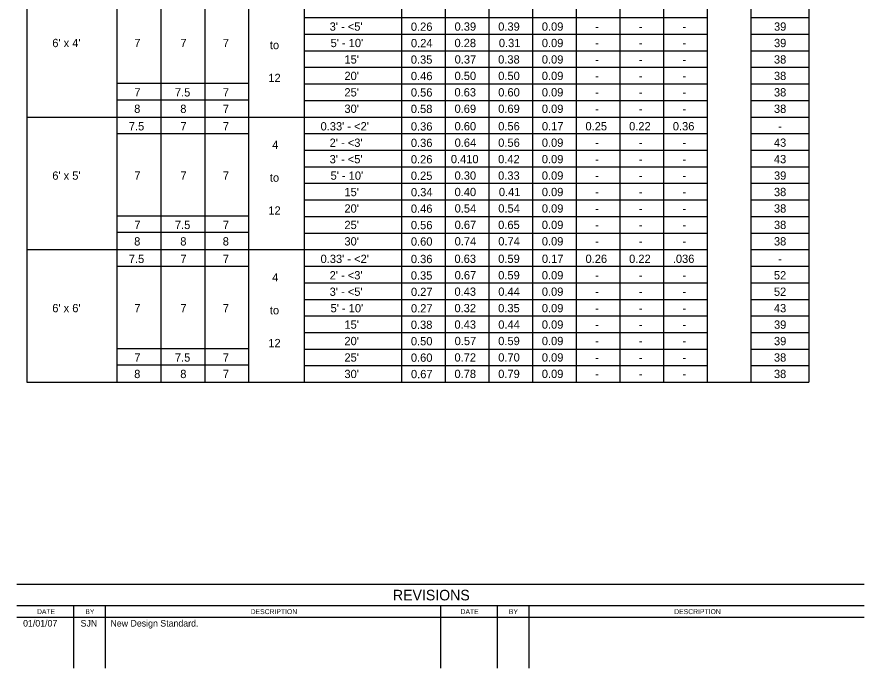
# Model space of a CAD drawing. Extents: x 10340.93 to 10343.14, y 76399.51 to 76400.59.
# Drawn here: x 10340.931 to 10341.575, y 76399.507 to 76400.002 of the extents above; entities that cross this region are included whole.
import ezdxf

# ---------------------------------------------------------------- set-up
doc = ezdxf.new("R2010")
doc.units = 0
for name, color, linetype in [('AdhocPoint_dp', 7, 'Continuous'), ('Border', 7, 'Continuous'), ('PlotBorder_dp', 7, 'Continuous')]:
    doc.layers.add(name, color=color, linetype=linetype)

msp = doc.modelspace()

# ---------------------------------------------------------------- linework, layer by layer
at = {"layer": 'Border'}
for p, q in [((10341.57483, 76399.57), (10340.93072, 76399.57)), ((10341.57483, 76399.5539), (10340.93072, 76399.5539)), ((10340.97374, 76399.5539), (10340.97374, 76399.50656)), ((10340.99791, 76399.5539), (10340.99791, 76399.50656)), ((10341.25278, 76399.5539), (10341.25278, 76399.50656)), ((10341.2958, 76399.5539), (10341.2958, 76399.50656)), ((10341.31997, 76399.5539), (10341.31997, 76399.50656)), ((10340.93072, 76399.54537), (10341.57483, 76399.54537))]:
    msp.add_line(p, q, dxfattribs=at)
at = {"layer": 'PlotBorder_dp'}
for p, q in [((10340.93815, 76400.49971), (10340.93815, 76399.72389)), ((10341.53289, 76400.49971), (10341.53289, 76399.72389)), ((10341.00679, 76400.47984), (10341.00679, 76399.72389)), ((10341.14923, 76400.47984), (10341.14923, 76399.72389)), ((10341.22311, 76400.47984), (10341.22311, 76399.72389)), ((10341.4887, 76400.47984), (10341.4887, 76399.72389)), ((10341.04015, 76400.46724), (10341.04015, 76399.72389)), ((10341.07351, 76400.46724), (10341.07351, 76399.72389)), ((10341.10687, 76400.46724), (10341.10687, 76399.72389)), ((10341.25631, 76400.44209), (10341.25631, 76399.72389)), ((10341.28951, 76400.44209), (10341.28951, 76399.72389)), ((10341.32271, 76400.44209), (10341.32271, 76399.72389)), ((10341.35591, 76400.44209), (10341.35591, 76399.72389)), ((10341.3891, 76400.44209), (10341.3891, 76399.72389)), ((10341.3891, 76400.44209), (10341.3891, 76399.72389)), ((10341.4223, 76400.44209), (10341.4223, 76399.72389)), ((10341.4555, 76400.44209), (10341.4555, 76399.72389)), ((10341.14923, 76400.00109), (10341.4555, 76400.00109)), ((10341.4887, 76400.00109), (10341.53289, 76400.00109)), ((10341.14923, 76399.98849), (10341.4555, 76399.98849)), ((10341.4887, 76399.98849), (10341.53289, 76399.98849)), ((10341.14923, 76399.97589), (10341.4555, 76399.97589)), ((10341.4887, 76399.97589), (10341.53289, 76399.97589)), ((10341.14923, 76399.96329), (10341.4555, 76399.96329)), ((10341.4887, 76399.96329), (10341.53289, 76399.96329)), ((10341.00679, 76399.95117), (10341.10687, 76399.95117)), ((10341.14923, 76399.95069), (10341.4555, 76399.95069)), ((10341.4887, 76399.95069), (10341.53289, 76399.95069)), ((10341.00679, 76399.93867), (10341.10687, 76399.93867)), ((10341.14923, 76399.93809), (10341.4555, 76399.93809)), ((10341.4887, 76399.93809), (10341.53289, 76399.93809)), ((10340.93815, 76399.92549), (10341.4555, 76399.92549)), ((10341.14985, 76399.92549), (10341.22203, 76399.92549)), ((10341.14985, 76399.92549), (10341.22203, 76399.92549)), ((10341.4887, 76399.92549), (10341.53289, 76399.92549)), ((10341.00679, 76399.91289), (10341.10687, 76399.91289)), ((10341.14923, 76399.91289), (10341.4555, 76399.91289)), ((10341.4887, 76399.91289), (10341.53289, 76399.91289)), ((10341.14923, 76399.90029), (10341.4555, 76399.90029)), ((10341.4887, 76399.90029), (10341.53289, 76399.90029)), ((10341.14923, 76399.88769), (10341.4555, 76399.88769)), ((10341.4887, 76399.88769), (10341.53289, 76399.88769)), ((10341.14923, 76399.87509), (10341.4555, 76399.87509)), ((10341.4887, 76399.87509), (10341.53289, 76399.87509)), ((10341.14923, 76399.86249), (10341.4555, 76399.86249)), ((10341.4887, 76399.86249), (10341.53289, 76399.86249)), ((10341.00679, 76399.85037), (10341.10687, 76399.85037)), ((10341.14923, 76399.84989), (10341.4555, 76399.84989)), ((10341.4887, 76399.84989), (10341.53289, 76399.84989)), ((10341.00679, 76399.83787), (10341.10687, 76399.83787)), ((10341.14923, 76399.83729), (10341.4555, 76399.83729)), ((10341.4887, 76399.83729), (10341.53289, 76399.83729)), ((10340.93815, 76399.82469), (10341.4555, 76399.82469)), ((10341.14985, 76399.82469), (10341.22203, 76399.82469)), ((10341.14985, 76399.82469), (10341.22203, 76399.82469)), ((10341.14985, 76399.82469), (10341.22203, 76399.82469)), ((10341.4887, 76399.82469), (10341.53289, 76399.82469)), ((10341.00679, 76399.81209), (10341.10687, 76399.81209)), ((10341.14923, 76399.81209), (10341.4555, 76399.81209)), ((10341.4887, 76399.81209), (10341.53289, 76399.81209)), ((10341.14923, 76399.79949), (10341.4555, 76399.79949)), ((10341.4887, 76399.79949), (10341.53289, 76399.79949)), ((10341.14923, 76399.78689), (10341.4555, 76399.78689)), ((10341.4887, 76399.78689), (10341.53289, 76399.78689)), ((10341.14923, 76399.77429), (10341.4555, 76399.77429)), ((10341.4887, 76399.77429), (10341.53289, 76399.77429)), ((10341.14923, 76399.76169), (10341.4555, 76399.76169)), ((10341.4887, 76399.76169), (10341.53289, 76399.76169)), ((10341.00679, 76399.74957), (10341.10687, 76399.74957)), ((10341.14923, 76399.74909), (10341.4555, 76399.74909)), ((10341.4887, 76399.74909), (10341.53289, 76399.74909)), ((10341.00679, 76399.73707), (10341.10687, 76399.73707)), ((10341.14923, 76399.73649), (10341.4555, 76399.73649)), ((10341.4887, 76399.73649), (10341.53289, 76399.73649)), ((10340.93815, 76399.72389), (10341.53289, 76399.72389)), ((10341.14985, 76399.72389), (10341.22203, 76399.72389))]:
    msp.add_line(p, q, dxfattribs=at)

# ---------------------------------------------------------------- texts
at = {"layer": 'AdhocPoint_dp'}
for s, height, p in [('REVISIONS', 0.008022, (10341.21661, 76399.55802)), ('BY', 0.003753, (10340.98272, 76399.54758)), ('BY', 0.003753, (10341.30479, 76399.54758)), ('01/01/07', 0.005, (10340.93539, 76399.53811)), ('SJN', 0.005, (10340.97912, 76399.53811)), ('New Design Standard.', 0.005, (10341.00182, 76399.53811))]:
    msp.add_text(s, height=height, dxfattribs=at).set_placement(p)
for s, height, rotation, p in [('DATE', 0.003737, 359.86925, (10340.94598, 76399.5476)), ('DESCRIPTION', 0.0037522, 0.04975, (10341.10841, 76399.54756)), ('DATE', 0.003737, 359.86925, (10341.26805, 76399.5476)), ('DESCRIPTION', 0.0037522, 0.04975, (10341.43048, 76399.54756))]:
    msp.add_text(s, height=height, rotation=rotation, dxfattribs=at).set_placement(p)
at = {"layer": 'PlotBorder_dp'}
for s, p in [("3' - <5'", (10341.16849, 76399.99114)), ('0.26', (10341.23025, 76399.99104)), ('0.39', (10341.26345, 76399.99114)), ('0.39', (10341.29665, 76399.99114)), ('0.09', (10341.32981, 76399.99114)), ('-', (10341.37038, 76399.99114)), ('-', (10341.40359, 76399.99114)), ('-', (10341.43677, 76399.99114)), ('39', (10341.50636, 76399.99114)), ("6' x 4'", (10340.95759, 76399.97864)), ('7', (10341.01998, 76399.97862)), ('7', (10341.05502, 76399.97862)), ('7', (10341.08731, 76399.97862)), ("5' - 10'", (10341.1692, 76399.97864)), ('0.24', (10341.23031, 76399.97854)), ('0.28', (10341.2634, 76399.97864)), ('0.31', (10341.29715, 76399.97864)), ('0.09', (10341.32981, 76399.97864)), ('39', (10341.50636, 76399.97864)), ('to', (10341.12303, 76399.97709)), ('-', (10341.37038, 76399.97864)), ('-', (10341.40359, 76399.97864)), ('-', (10341.43677, 76399.97864)), ("15'", (10341.17972, 76399.96614)), ('0.35', (10341.23021, 76399.96604)), ('0.37', (10341.26353, 76399.96614)), ('0.38', (10341.2966, 76399.96614)), ('0.09', (10341.32981, 76399.96614)), ('38', (10341.50631, 76399.96614)), ('-', (10341.37038, 76399.96614)), ('-', (10341.40359, 76399.96614)), ('-', (10341.43677, 76399.96614)), ("20'", (10341.17972, 76399.95364)), ('0.46', (10341.23025, 76399.95354)), ('0.50', (10341.26346, 76399.95364)), ('0.50', (10341.29667, 76399.95364)), ('0.09', (10341.32981, 76399.95364)), ('38', (10341.50631, 76399.95364)), ('12', (10341.12186, 76399.95209)), ('-', (10341.37038, 76399.95364)), ('-', (10341.40359, 76399.95364)), ('-', (10341.43677, 76399.95364)), ('7', (10341.01998, 76399.94112)), ('7.5', (10341.05084, 76399.94112)), ('7', (10341.08731, 76399.94112)), ("25'", (10341.17972, 76399.94114)), ('0.56', (10341.23025, 76399.94104)), ('0.63', (10341.26338, 76399.94114)), ('0.60', (10341.29667, 76399.94114)), ('0.09', (10341.32981, 76399.94114)), ('38', (10341.50631, 76399.94114)), ('-', (10341.37038, 76399.94114)), ('-', (10341.40359, 76399.94114)), ('-', (10341.43677, 76399.94114)), ('8', (10341.01986, 76399.92862)), ('8', (10341.0549, 76399.92862)), ('7', (10341.08731, 76399.92862)), ("30'", (10341.17972, 76399.92864)), ('0.58', (10341.23021, 76399.92854)), ('0.69', (10341.26345, 76399.92864)), ('0.69', (10341.29665, 76399.92864)), ('0.09', (10341.32981, 76399.92864)), ('38', (10341.50631, 76399.92864)), ('-', (10341.37038, 76399.92864)), ('-', (10341.40359, 76399.92864)), ('-', (10341.43677, 76399.92864)), ('7.5', (10341.0158, 76399.91532)), ('7', (10341.05502, 76399.91532)), ('7', (10341.08731, 76399.91532)), ("0.33' - <2'", (10341.16159, 76399.91531)), ('0.36', (10341.23025, 76399.91521)), ('0.60', (10341.26346, 76399.91536)), ('0.56', (10341.29665, 76399.91536)), ('0.17', (10341.32989, 76399.91536)), ('0.25', (10341.363, 76399.91536)), ('0.22', (10341.39619, 76399.91536)), ('0.36', (10341.42943, 76399.91536)), ('-', (10341.50962, 76399.91536)), ('4', (10341.12481, 76399.90129)), ("2' - <3'", (10341.16849, 76399.90281)), ('0.36', (10341.23025, 76399.90271)), ('0.64', (10341.26351, 76399.90286)), ('0.56', (10341.29665, 76399.90286)), ('0.09', (10341.32981, 76399.90286)), ('43', (10341.50629, 76399.90286)), ('-', (10341.37038, 76399.90286)), ('-', (10341.40359, 76399.90286)), ('-', (10341.43677, 76399.90286)), ("3' - <5'", (10341.16849, 76399.89031)), ('0.26', (10341.23025, 76399.89021)), ('0.410', (10341.26064, 76399.89036)), ('0.42', (10341.29659, 76399.89036)), ('0.09', (10341.32981, 76399.89036)), ('43', (10341.50629, 76399.89036)), ('-', (10341.37038, 76399.89036)), ('-', (10341.40359, 76399.89036)), ('-', (10341.43677, 76399.89036)), ("6' x 5'", (10340.95759, 76399.87781)), ('7', (10341.01998, 76399.87782)), ('7', (10341.05502, 76399.87782)), ('7', (10341.08731, 76399.87782)), ('to', (10341.12303, 76399.87629)), ("5' - 10'", (10341.1692, 76399.87781)), ('0.25', (10341.23021, 76399.87771)), ('0.30', (10341.26346, 76399.87786)), ('0.33', (10341.29658, 76399.87786)), ('0.09', (10341.32981, 76399.87786)), ('39', (10341.50636, 76399.87786)), ('-', (10341.37038, 76399.87786)), ('-', (10341.40359, 76399.87786)), ('-', (10341.43677, 76399.87786)), ("15'", (10341.17972, 76399.86531)), ('0.34', (10341.23031, 76399.86521)), ('0.40', (10341.26346, 76399.86536)), ('0.41', (10341.29715, 76399.86536)), ('0.09', (10341.32981, 76399.86536)), ('38', (10341.50631, 76399.86536)), ('-', (10341.37038, 76399.86536)), ('-', (10341.40359, 76399.86536)), ('-', (10341.43677, 76399.86536)), ('12', (10341.12186, 76399.85129)), ("20'", (10341.17972, 76399.85281)), ('0.46', (10341.23025, 76399.85271)), ('0.54', (10341.26351, 76399.85286)), ('0.54', (10341.29671, 76399.85286)), ('0.09', (10341.32981, 76399.85286)), ('38', (10341.50631, 76399.85286)), ('-', (10341.37038, 76399.85286)), ('-', (10341.40359, 76399.85286)), ('-', (10341.43677, 76399.85286)), ('7', (10341.01998, 76399.84032)), ('7.5', (10341.05084, 76399.84032)), ('7', (10341.08731, 76399.84032)), ("25'", (10341.17972, 76399.84031)), ('0.56', (10341.23025, 76399.84021)), ('0.67', (10341.26353, 76399.84036)), ('0.65', (10341.29661, 76399.84036)), ('0.09', (10341.32981, 76399.84036)), ('-', (10341.37038, 76399.84036)), ('-', (10341.40359, 76399.84036)), ('-', (10341.43677, 76399.84036)), ('38', (10341.50631, 76399.84036)), ('8', (10341.01986, 76399.82782)), ('8', (10341.0549, 76399.82782)), ('8', (10341.08719, 76399.82782)), ("30'", (10341.17972, 76399.82781)), ('0.60', (10341.23027, 76399.82771)), ('0.74', (10341.26351, 76399.82786)), ('0.74', (10341.29671, 76399.82786)), ('0.09', (10341.32981, 76399.82786)), ('-', (10341.37038, 76399.82786)), ('-', (10341.40359, 76399.82786)), ('-', (10341.43677, 76399.82786)), ('38', (10341.50631, 76399.82786)), ('7.5', (10341.0158, 76399.81452)), ('7', (10341.05502, 76399.81452)), ('7', (10341.08731, 76399.81452)), ("0.33' - <2'", (10341.16159, 76399.81453)), ('0.36', (10341.23025, 76399.81442)), ('0.63', (10341.26338, 76399.81458)), ('0.59', (10341.29665, 76399.81458)), ('0.17', (10341.32989, 76399.81458)), ('0.26', (10341.36304, 76399.81458)), ('0.22', (10341.39619, 76399.81458)), ('.036', (10341.42943, 76399.81458)), ('-', (10341.50962, 76399.81453)), ('4', (10341.12481, 76399.80049)), ("2' - <3'", (10341.16849, 76399.80203)), ('0.35', (10341.23021, 76399.80192)), ('0.67', (10341.26353, 76399.80208)), ('0.59', (10341.29665, 76399.80208)), ('0.09', (10341.32981, 76399.80208)), ('-', (10341.37038, 76399.80208)), ('-', (10341.40359, 76399.80208)), ('-', (10341.43677, 76399.80208)), ('52', (10341.50629, 76399.80203)), ("3' - <5'", (10341.16849, 76399.78953)), ('0.27', (10341.23033, 76399.78942)), ('0.43', (10341.26338, 76399.78958)), ('0.44', (10341.29671, 76399.78958)), ('0.09', (10341.32981, 76399.78958)), ('-', (10341.37038, 76399.78958)), ('-', (10341.40359, 76399.78958)), ('-', (10341.43677, 76399.78958)), ('52', (10341.50629, 76399.78953)), ("6' x 6'", (10340.95759, 76399.77708)), ('7', (10341.01998, 76399.77702)), ('7', (10341.05502, 76399.77702)), ('7', (10341.08731, 76399.77702)), ('to', (10341.12303, 76399.77549)), ("5' - 10'", (10341.1692, 76399.77703)), ('0.27', (10341.23033, 76399.77692)), ('0.32', (10341.26339, 76399.77708)), ('0.35', (10341.29661, 76399.77708)), ('0.09', (10341.32981, 76399.77708)), ('-', (10341.37038, 76399.77708)), ('-', (10341.40359, 76399.77708)), ('-', (10341.43677, 76399.77708)), ('43', (10341.50629, 76399.77703)), ("15'", (10341.17972, 76399.76453)), ('0.38', (10341.23021, 76399.76442)), ('0.43', (10341.26338, 76399.76458)), ('0.44', (10341.29671, 76399.76458)), ('0.09', (10341.32981, 76399.76458)), ('-', (10341.37038, 76399.76458)), ('-', (10341.40359, 76399.76458)), ('-', (10341.43677, 76399.76458)), ('39', (10341.50636, 76399.76453)), ('12', (10341.12186, 76399.75049)), ("20'", (10341.17972, 76399.75203)), ('0.50', (10341.23027, 76399.75192)), ('0.57', (10341.26353, 76399.75208)), ('0.59', (10341.29665, 76399.75208)), ('0.09', (10341.32981, 76399.75208)), ('-', (10341.37038, 76399.75208)), ('-', (10341.40359, 76399.75208)), ('-', (10341.43677, 76399.75208)), ('39', (10341.50636, 76399.75203)), ('7', (10341.01998, 76399.73952)), ('7.5', (10341.05084, 76399.73952)), ('7', (10341.08731, 76399.73952)), ("25'", (10341.17972, 76399.73953)), ('0.60', (10341.23027, 76399.73942)), ('0.72', (10341.26339, 76399.73958)), ('0.70', (10341.29667, 76399.73958)), ('0.09', (10341.32981, 76399.73958)), ('-', (10341.37038, 76399.73958)), ('-', (10341.40359, 76399.73958)), ('-', (10341.43677, 76399.73958)), ('38', (10341.50631, 76399.73953)), ('8', (10341.01986, 76399.72702)), ('8', (10341.0549, 76399.72702)), ('7', (10341.08731, 76399.72702)), ("30'", (10341.17972, 76399.72703)), ('0.67', (10341.23033, 76399.72692)), ('0.78', (10341.2634, 76399.72708)), ('0.79', (10341.29665, 76399.72708)), ('0.09', (10341.32981, 76399.72708)), ('-', (10341.37038, 76399.72708)), ('-', (10341.40359, 76399.72708)), ('-', (10341.43677, 76399.72708)), ('38', (10341.50631, 76399.72703))]:
    msp.add_text(s, height=0.0063, dxfattribs=at).set_placement(p)

doc.saveas('drawing.dxf')
